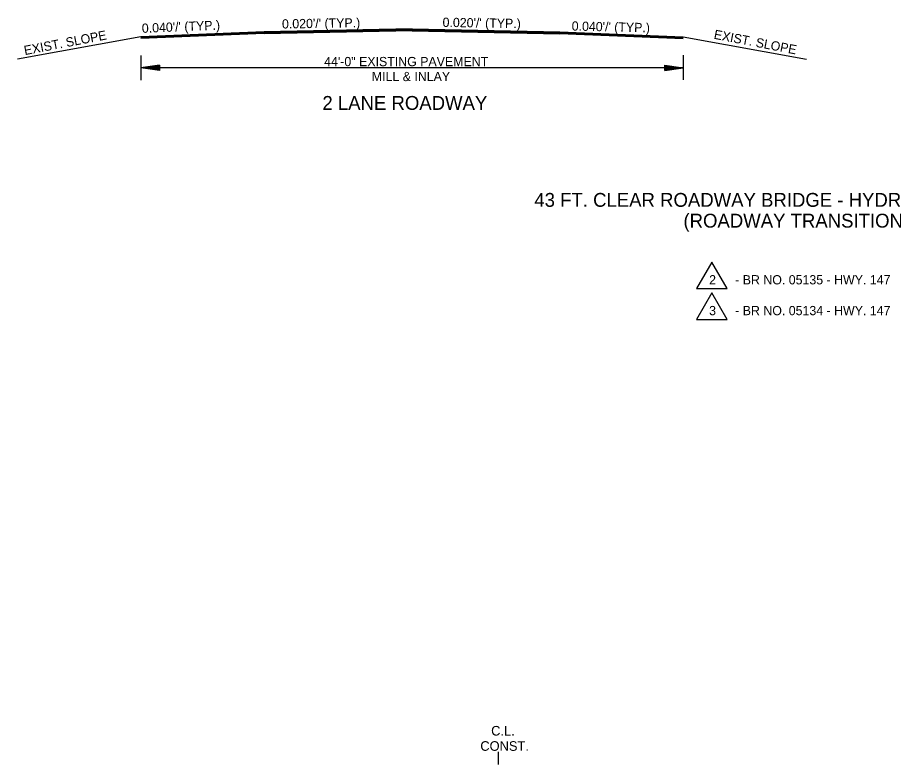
# Model space of a CAD drawing. Extents: x 549600 to 1930787, y -1955432 to 596640.
# Drawn here: x 550982 to 551693, y -1945743 to -1945137 of the extents above; entities that cross this region are included whole.
import ezdxf

# ---------------------------------------------------------------- set-up
doc = ezdxf.new("R2010")
doc.units = 0
doc.layers.add('R_Border', color=7, linetype='Continuous')
doc.layers.add('S_AREA_CALC', color=7, linetype='Continuous')

msp = doc.modelspace()

# ---------------------------------------------------------------- linework, layer by layer
at = {"layer": 'R_Border'}
for p, q in [((551532.75, -1945356.71), (551557.54, -1945356.71)), ((551532.75, -1945381.71), (551557.54, -1945381.71))]:
    msp.add_line(p, q, dxfattribs=at)
for points in [[(551557.54, -1945356.71), (551545.14, -1945335.24), (551532.75, -1945356.71)], [(551557.54, -1945381.71), (551545.14, -1945360.24), (551532.75, -1945381.71)]]:
    msp.add_lwpolyline(points, dxfattribs=at)
at = {"layer": 'S_AREA_CALC'}
for p, q in [((551182.02, -1945148.27), (551082.02, -1945152.27)), ((551182.02, -1945148.57), (551082.02, -1945152.57)), ((551182.02, -1945148.87), (551082.02, -1945152.87)), ((551182.02, -1945149.17), (551082.02, -1945153.17)), ((551302.02, -1945145.87), (551182.02, -1945148.27)), ((551302.02, -1945146.17), (551182.02, -1945148.57)), ((551302.02, -1945146.47), (551182.02, -1945148.87)), ((551302.02, -1945146.77), (551182.02, -1945149.17)), ((551302.02, -1945147.07), (551182.02, -1945149.47)), ((551302.02, -1945147.37), (551182.02, -1945149.77)), ((551302.02, -1945147.54), (551182.02, -1945149.94)), ((551302.02, -1945145.87), (551422.02, -1945148.27)), ((551302.02, -1945146.17), (551422.02, -1945148.57)), ((551302.02, -1945146.47), (551422.02, -1945148.87)), ((551302.02, -1945146.77), (551422.02, -1945149.17)), ((551302.02, -1945147.07), (551422.02, -1945149.47)), ((551302.02, -1945147.37), (551422.02, -1945149.77)), ((551302.02, -1945147.54), (551422.02, -1945149.94)), ((551422.02, -1945148.27), (551522.02, -1945152.27)), ((551422.02, -1945148.57), (551522.02, -1945152.57)), ((551422.02, -1945148.87), (551522.02, -1945152.87)), ((551422.02, -1945149.17), (551522.02, -1945153.17)), ((551082.02, -1945152.27), (550981.95, -1945170.65)), ((551182.02, -1945149.47), (551082.02, -1945153.47)), ((551182.02, -1945149.77), (551082.02, -1945153.77)), ((551422.02, -1945149.47), (551522.02, -1945153.47)), ((551422.02, -1945149.77), (551522.02, -1945153.77)), ((551522.02, -1945152.27), (551622.09, -1945170.65)), ((551082.02, -1945167.53), (551082.02, -1945187.53)), ((551522.02, -1945167.28), (551522.02, -1945187.28)), ((551097.02, -1945175.28), (551082.02, -1945177.53)), ((551097.02, -1945179.78), (551082.02, -1945177.53)), ((551522.02, -1945177.53), (551082.02, -1945177.53)), ((551097.02, -1945175.65), (551084.52, -1945177.53)), ((551097.02, -1945179.4), (551084.52, -1945177.53)), ((551097.02, -1945176.04), (551087.1, -1945177.53)), ((551097.02, -1945179.02), (551087.1, -1945177.53)), ((551097.02, -1945176.41), (551089.6, -1945177.53)), ((551097.02, -1945178.65), (551089.6, -1945177.53)), ((551097.02, -1945176.8), (551092.14, -1945177.53)), ((551097.02, -1945178.26), (551092.14, -1945177.53)), ((551097.02, -1945177.18), (551094.65, -1945177.53)), ((551097.02, -1945177.88), (551094.65, -1945177.53)), ((551097.02, -1945175.28), (551097.02, -1945179.78)), ((551507.02, -1945175.28), (551522.02, -1945177.53)), ((551507.02, -1945179.78), (551507.02, -1945175.28)), ((551507.02, -1945175.65), (551519.51, -1945177.53)), ((551507.02, -1945176.04), (551516.93, -1945177.53)), ((551507.02, -1945176.41), (551514.44, -1945177.53)), ((551507.02, -1945176.79), (551511.89, -1945177.53)), ((551507.02, -1945177.18), (551509.39, -1945177.53)), ((551507.02, -1945179.78), (551522.02, -1945177.53)), ((551507.02, -1945178.26), (551511.89, -1945177.53)), ((551507.02, -1945179.02), (551516.93, -1945177.53)), ((551507.02, -1945179.4), (551519.51, -1945177.53)), ((551507.02, -1945178.65), (551514.44, -1945177.53)), ((551507.02, -1945177.88), (551509.39, -1945177.53)), ((551372.02, -1945742.94), (551372.02, -1945732.56))]:
    msp.add_line(p, q, dxfattribs=at)

# ---------------------------------------------------------------- texts
at = {"layer": 'R_Border'}
for s, p in [('2', (551543.02, -1945353.31)), ('- BR NO. 05135 - HWY. 147', (551564.14, -1945353.31)), ('3', (551543.02, -1945378.31)), ('- BR NO. 05134 - HWY. 147', (551564.14, -1945378.31))]:
    msp.add_text(s, height=7.5, dxfattribs=at).set_placement(p)
at = {"layer": 'S_AREA_CALC'}
for s, rotation, p in [("  0.040'/' (TYP.)", 2.44797, (551077.39, -1945149.47)), ("0.020'/' (TYP.)", 0.97192, (551196.54, -1945145.67)), ("0.020'/' (TYP.)", 359.02808, (551326.72, -1945144.29)), ("0.040'/' (TYP.)", 358.68162, (551431.46, -1945147.3)), ('EXIST. SLOPE', 10.88286, (550987.93, -1945167.27)), ('EXIST. SLOPE', 349.11714, (551546.4, -1945153.87))]:
    msp.add_text(s, height=7.5, rotation=rotation, dxfattribs=at).set_placement(p)
for s, height, p in [('44\'-0" EXISTING PAVEMENT ', 7.5, (551230.69, -1945176.21)), ('MILL & INLAY', 7.5, (551269.34, -1945188.31)), ('2 LANE ROADWAY', 11.25, (551229.29, -1945211.67)), ('43 FT. CLEAR ROADWAY BRIDGE - HYDRODEMOLITION', 11.25, (551401.23, -1945290.35)), ('(ROADWAY TRANSITIONS)', 11.25, (551522.18, -1945307.22)), ('C.L.', 7.8, (551366.17, -1945719.47)), ('CONST.', 7.8, (551357.39, -1945731.84))]:
    msp.add_text(s, height=height, dxfattribs=at).set_placement(p)

doc.saveas('drawing.dxf')
